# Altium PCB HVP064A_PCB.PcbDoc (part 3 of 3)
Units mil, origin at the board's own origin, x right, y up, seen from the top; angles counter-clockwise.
Board outline 5750 x 4500 mil, 2 copper layers (Top Layer, Bottom Layer), stack 62 mil thick; 174 components, 71 nets, 376 pads, 361 vias.
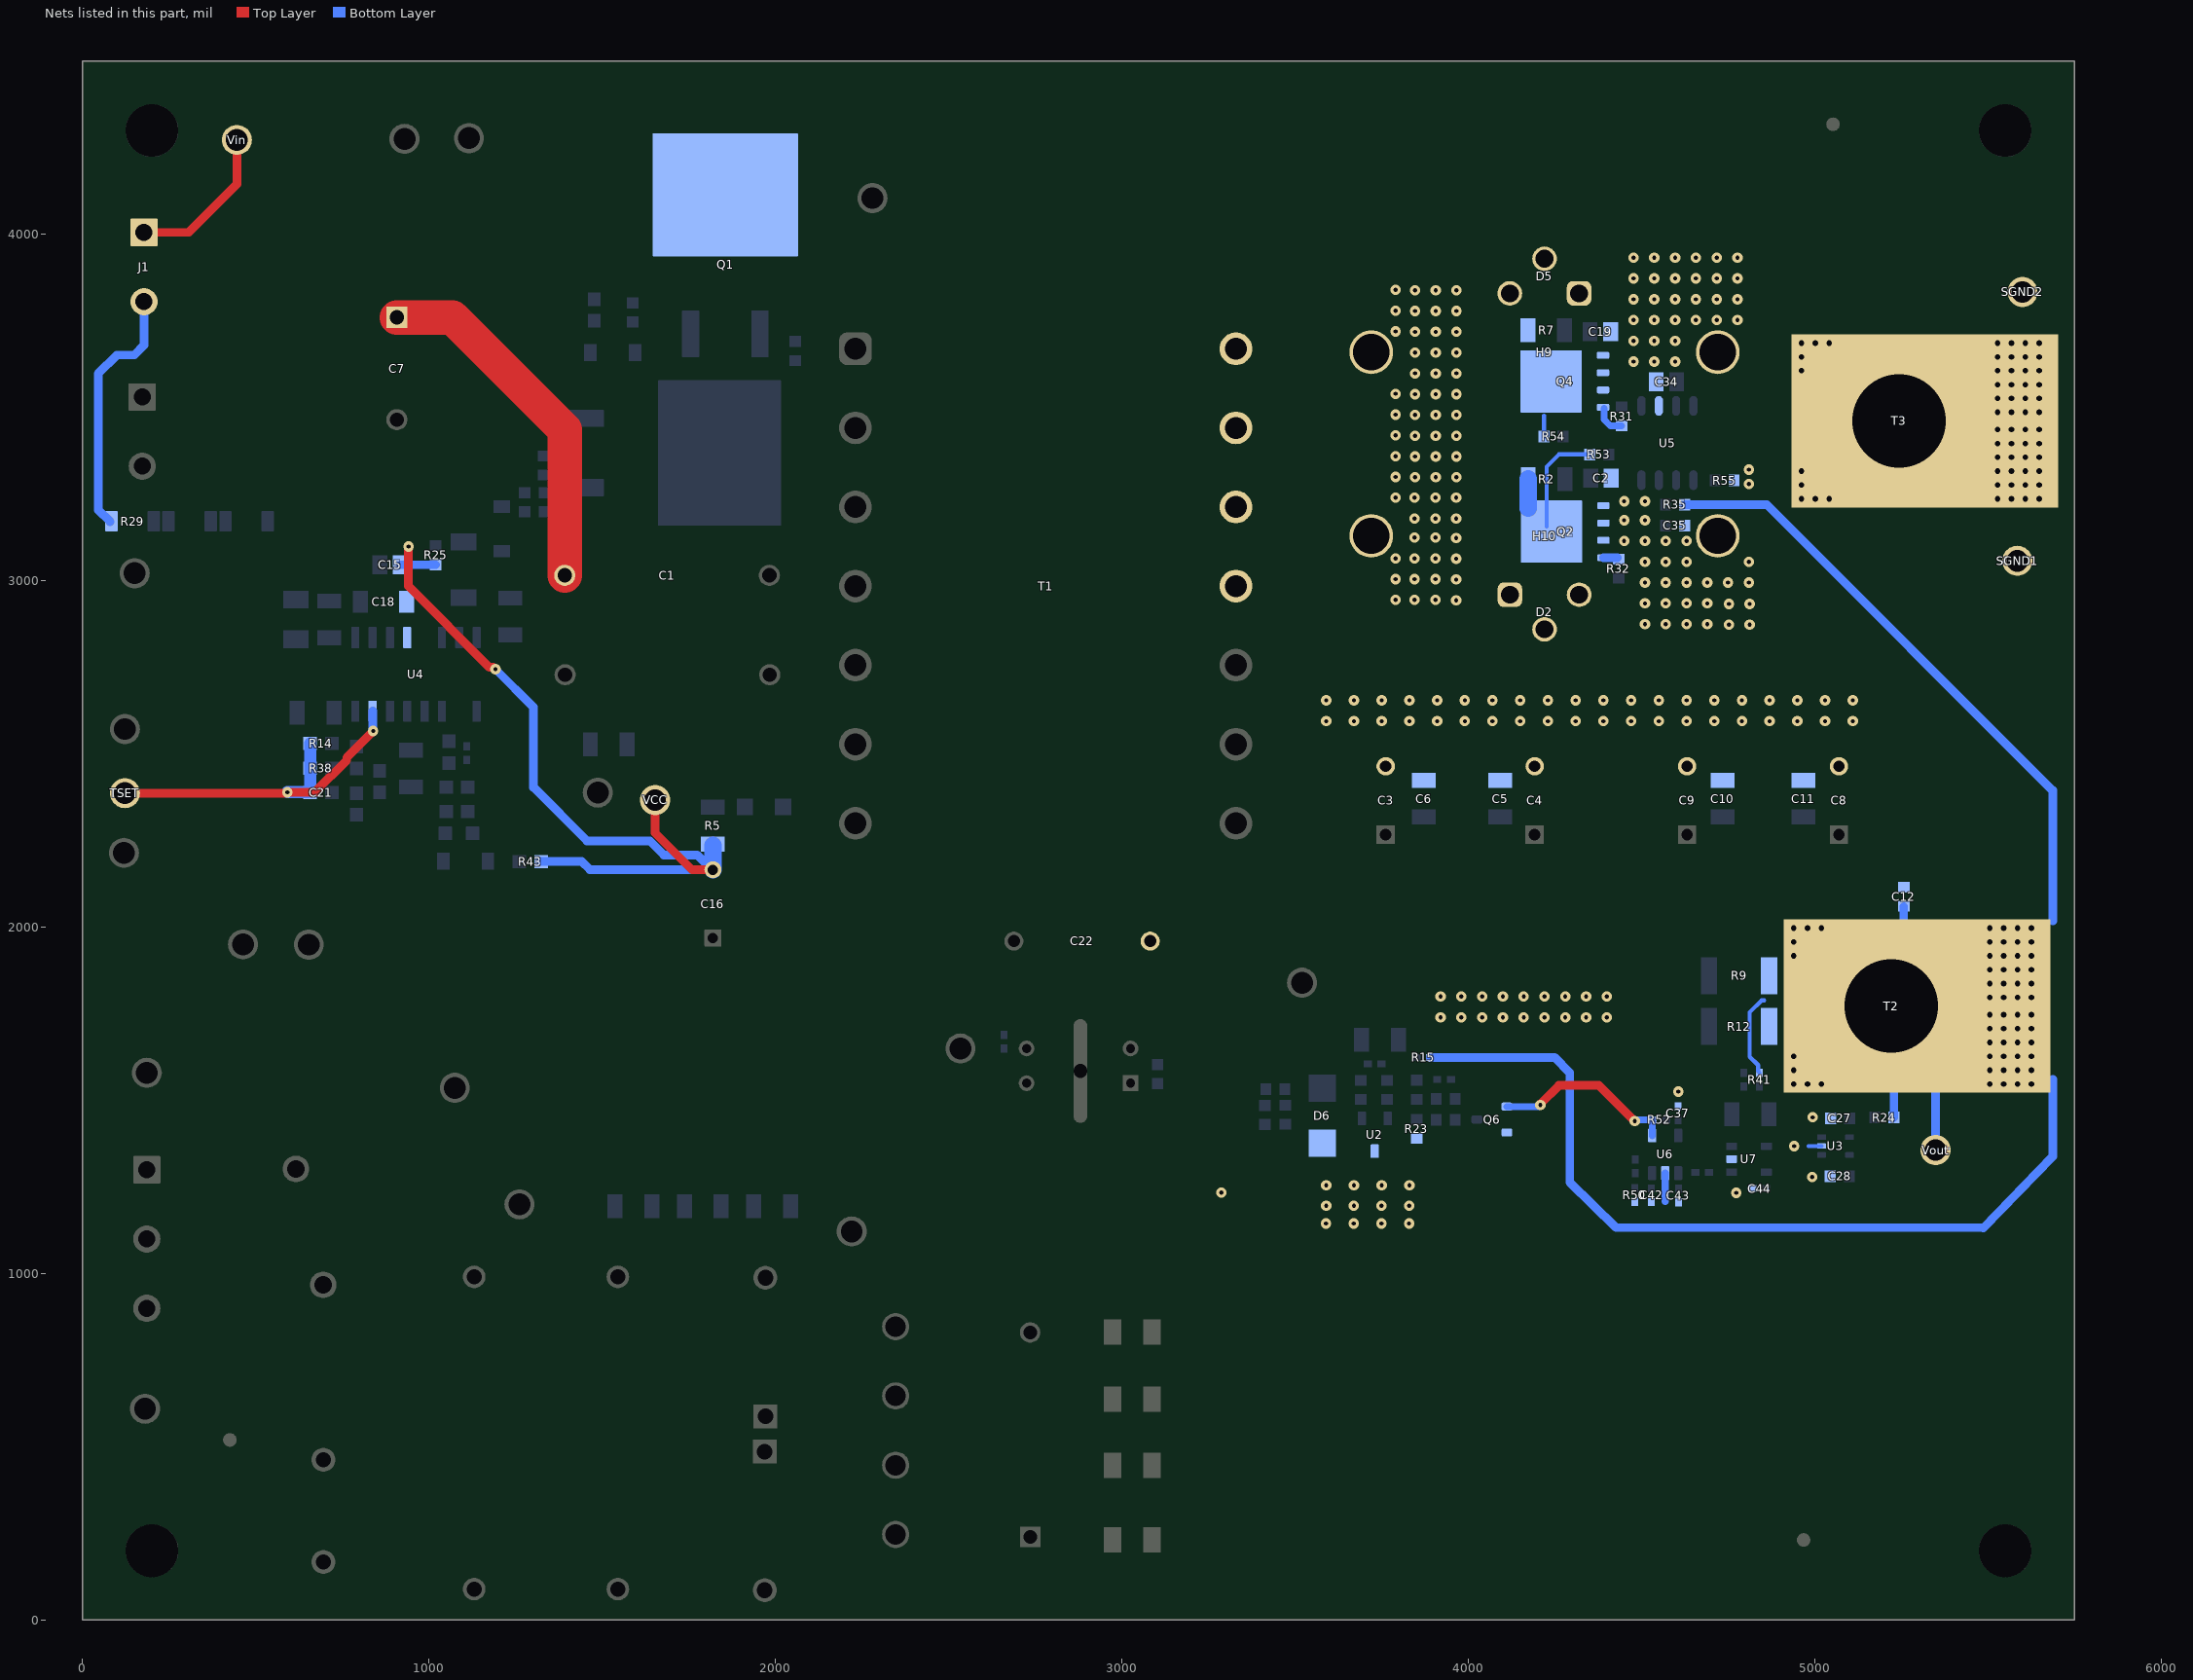
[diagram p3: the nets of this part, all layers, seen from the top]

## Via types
v1: diameter 30, hole 12, Top Layer to Bottom Layer, 243 vias
v2: diameter 32, hole 16, Top Layer to Bottom Layer, 116 vias
v3: diameter 34, hole 16, Top Layer to Bottom Layer, 2 vias

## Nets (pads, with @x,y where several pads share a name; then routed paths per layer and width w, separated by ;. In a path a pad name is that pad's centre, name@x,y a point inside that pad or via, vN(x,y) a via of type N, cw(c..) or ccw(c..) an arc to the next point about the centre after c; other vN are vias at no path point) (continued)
SGND: C2.2 C3.2 C4.2 C5.1 C6.1 C8.2 C9.2 C10.2 C11.2 C12.2 C19.2 C22.1 C27.2 C28.2 C34.2 C35.2 C37.2 C42.1 C43.2 C44.2 D2.1 D2.3 D5.1 D5.3 D6.2 H9.1 H9.2 H10.1 H10.2 Q2.1 Q2.2 Q2.3 Q4.1 Q4.2 Q4.3 Q6.2 R23.1 R50.1 R55.2 SGND1.1 SGND2.1 T3.1 U2.3 U3.2 U5.2 U6.2 U7.2 | length 119.5
  Bottom Layer w12: 4982.39,1368.33 U3.2@5020.03,1368.33
  Bottom Layer w20: 4568.39,1208.33 U6.2@4568.39,1290.2
  other v1: 3589,1145 3669,1145 3749,1145 3829,1145 3589.63,1195.83 3669.63,1195.83 3749.63,1195.83 3829.63,1195.83 4773.39,1233.33 3287,1234 3590,1255 3670,1255 3750,1255 3830,1255 4992.39,1279.33 4940.39,1368.33 4994.39,1451.33 4606.39,1525.33 3920,1740 3980,1740 4040,1740 4100,1740 4160,1740 4220,1740 4280,1740 4340,1740 4400,1740 3920,1800 3980,1800 4040,1800 4100,1800 4160,1800 4220,1800 4280,1800 4340,1800 4400,1800 3590,2595 3670,2595 3750,2595 3830,2595 3910,2595 3990,2595 4070,2595 4150,2595 4230,2595 4310,2595 4390,2595 4470,2595 4550,2595 4630,2595 4710,2595 4790,2595 4870,2595 4950,2595 5030,2595 5110,2595 3590,2655 3670,2655 3750,2655 3830,2655 3910,2655 3990,2655 4070,2655 4150,2655 4230,2655 4310,2655 4390,2655 4470,2655 4550,2655 4630,2655 4710,2655 4790,2655 4870,2655 4950,2655 5030,2655 5110,2655 4752.42,2873.37 4812.42,2873.37 4510,2875 4570,2875 4630,2875 4690,2875 4752.42,2933.37 4812.42,2933.37 4510,2935 4570,2935 4630,2935 4690,2935 3965,2943.83 3790,2945 3845,2945 3905,2945 4510,2995 4570,2995 4630,2995 4690,2995 4750,2995 4810,2995 3965,3003.83 3790,3005 3845,3005 3905,3005 4510,3055 4570,3055 4630,3055 4810,3055 3965,3063.83 3790,3065 3845,3065 3905,3065 4450,3115 4510,3115 4570,3115 4630,3115 3965,3123.83 3845,3125 3905,3125 4450,3175 4510,3175 3845,3180 3905,3180 3965,3180 4450,3230 4510,3230 3790,3240 3845,3240 3905,3240 3965,3240 4810,3280 3846,3299 3906,3299 3966,3299 3790,3300 4810,3320.89 3846,3359 3906,3359 3966,3359 3790,3360 3846,3419 3906,3419 3966,3419 3790,3420 3846,3479 3906,3479 3966,3479 3790,3480 3846,3539 3906,3539 3966,3539 3790,3540 3846,3599 3906,3599 3966,3599 4477,3633 4537,3633 4597,3633 3846,3659 3906,3659 3966,3659 4477,3693 4537,3693 4597,3693 3846,3719 3906,3719 3966,3719 3790,3720 4477,3753 4537,3753 4597,3753 4657,3753 4717,3753 4777,3753 3846,3779 3906,3779 3966,3779 3790,3780 4477,3813 4537,3813 4597,3813 4657,3813 4717,3813 4777,3813 3846,3839 3906,3839 3966,3839 3790,3840 4477,3873 4537,3873 4597,3873 4657,3873 4717,3873 4777,3873 4477,3933 4537,3933 4597,3933 4657,3933 4717,3933 4777,3933
  other v2: 4961.9,3236.62 5001.9,3236.62 5041.9,3236.62 5528.16,3236.62 5568.16,3236.62 5608.16,3236.62 5648.16,3236.62 4961.9,3276.62 5528.16,3276.62 5568.16,3276.62 5608.16,3276.62 5648.16,3276.62 4961.9,3316.62 5528.16,3316.62 5568.16,3316.62 5608.16,3316.62 5648.16,3316.62 5528.16,3356.62 5568.16,3356.62 5608.16,3356.62 5648.16,3356.62 5528.16,3396.62 5568.16,3396.62 5608.16,3396.62 5648.16,3396.62 5528.16,3436.62 5568.16,3436.62 5608.16,3436.62 5648.16,3436.62 5528.16,3486.62 5568.16,3486.62 5608.16,3486.62 5648.16,3486.62 5528.16,3526.62 5568.16,3526.62 5608.16,3526.62 5648.16,3526.62 5528.16,3566.62 5568.16,3566.62 5608.16,3566.62 5648.16,3566.62 4961.9,3606.62 5528.16,3606.62 5568.16,3606.62 5608.16,3606.62 5648.16,3606.62 4961.9,3646.62 5528.16,3646.62 5568.16,3646.62 5608.16,3646.62 5648.16,3646.62 4961.9,3686.62 5001.9,3686.62 5041.9,3686.62 5528.16,3686.62 5568.16,3686.62 5608.16,3686.62 5648.16,3686.62
Standby_Secondary: Q6.1 R52.1 U6.4 | length 533.5
  Top Layer w25: v1@4205.23,1486.77 v1(4208,1486.77) 4208,1489.54 4261.96,1543.5 4377.09,1543.5 v1(4480.39,1440.2)
  Bottom Layer w20: Q6.1@4111.31,1482.4 4203.63,1482.4 v1(4208,1486.77) ; v1@4485.89,1444.33 R52.1@4531.7,1444.33 4531.7,1399.18 U6.4@4530.99,1398.46
TSET/PFC_OFF: C21.1 R14.1 R38.2 TSET.1 U4.7 | length 1051.1
  Top Layer w25: TSET.1@121.87,2387.26 587.14,2387.26 589.65,2389.77 v1(591,2389.77) 669.76,2389.77 762.2,2482.21 762.2,2489.95 v1(838.64,2566.39)
  Bottom Layer w25: U4.7@837,2623.7 837.69,2623.01 837.69,2567.34 v1(838.64,2566.39)
  Bottom Layer w35: v1(591,2389.77) C21.1@650.03,2389.77 ; C21.1@656.67,2391.87 R38.2@656.67,2459.16 R14.1@656.67,2530.47
VCC: C15.1 C16.2 C18.1 R5.1 R25.1 R43.2 U4.12 VCC.1 | length 2450.1
  Top Layer w25: v1(940.45,3099) 940.45,2984.58 1174.46,2750.58 1184.63,2750.58 1190.13,2745.08 v1(1191.48,2745.08) ; VCC.1@1652.45,2367.2 1652.45,2272.19 1758.5,2166.14 C16.2@1819.55,2166.14
  Bottom Layer w25: C15.1@916.4,3046.51 938.05,3046.51 938.17,3046.39 R25.1@1019.15,3046.39 ; v1(1191.48,2745.08) 1301.31,2635.25 1301.31,2403.97 1456.22,2249.06 1637.14,2249.06 1677.73,2208.48 1774.07,2208.48 C16.2@1816.41,2166.14 ; R43.2@1323.26,2189.8 1441.02,2189.8 1464.68,2166.14 C16.2@1816.41,2166.14 ; C16.2@1819.55,2166.14 C16.2@1816.41,2166.14
  Bottom Layer w50: R5.1@1819.55,2236.41 C16.2@1819.55,2166.14
VD1: D5.2 Q4.5 Q4.6 Q4.7 Q4.8 Q4.9@4239.43,3576 R7.2 R54.2 T1.13 T1.14 | length 60.1
  Bottom Layer w12: R54.2@4218.44,3417 4218.44,3477.13
VD2: D2.2 Q2.5 Q2.6 Q2.7 Q2.8 Q2.9@4240.43,3142 R2.2 R53.1 T1.11 T1.12 | length 396.6
  Bottom Layer w12: Q2.9@4226,3156.43 4226,3329.41 4261.59,3365 R53.1@4350.44,3365
  Bottom Layer w50: Q2.8@4172.85,3209.58 R2.2@4172.85,3294
VG1: Q4.4 R31.1 | length 90.7
  Bottom Layer w20: Q4.4@4392.04,3498 4392.04,3465.96 4410.56,3447.44 R31.1@4443,3447.44
VG2: Q2.4 R32.2 | length 39.5
  Bottom Layer w25: Q2.4@4390.04,3067 R32.2@4429.56,3067
VIN: C1.1 C7.1 J1.1 J1.2 Q1.4 R29.2 Vin.1 | length 2226
  Top Layer w25: J1.1@177,4006 306,4006 445,4145 Vin.1@445,4273
  Top Layer w100: C7.1@907,3760.64 1067.36,3760.64 1391.72,3436.28 C1.1@1391.72,3016
  Bottom Layer w25: R29.2@79,3171 45,3205 45,3598 99,3652 149,3652 177,3680 J1.2@177,3806
Vout: C12.1 R9.2 R12.2 R15.2 R24.1 R35.2 R41.2 T2.1 Vout.1 | length 5062.7
  Bottom Layer w12: R41.2@4840.39,1580.01 4836.55,1583.86 4836.55,1602.08 4812.42,1626.21 4812.42,1754.36 4846.84,1788.78 4854.19,1788.78
  Bottom Layer w25: R15.2@3889.69,1624 4249,1624 4293,1580 4293,1264 4427,1133 5487,1132 5687.16,1338.09 5687.16,1561.01 ; R35.2@4624.56,3220 4862,3220 5687.21,2394.79 5687.21,2018.19 ; R24.1@5228.77,1451.03 T2.1@5228.77,1527.71 ; T2.1@5257,1933 C12.1@5257,2059.95 ; T2.1@5297.39,1555.33 T2.1@5297.39,1612.33 ; T2.1@5348.39,1640.83 Vout.1@5348.99,1356.9
  other v2: 4939.47,1547.33 4979.47,1547.33 5019.47,1547.33 5505.73,1547.33 5545.73,1547.33 5585.73,1547.33 5625.73,1547.33 4939.47,1587.33 5505.73,1587.33 5545.73,1587.33 5585.73,1587.33 5625.73,1587.33 4939.47,1627.33 5505.73,1627.33 5545.73,1627.33 5585.73,1627.33 5625.73,1627.33 5505.73,1667.33 5545.73,1667.33 5585.73,1667.33 5625.73,1667.33 5505.73,1707.33 5545.73,1707.33 5585.73,1707.33 5625.73,1707.33 5505.73,1747.33 5545.73,1747.33 5585.73,1747.33 5625.73,1747.33 5505.73,1797.33 5545.73,1797.33 5585.73,1797.33 5625.73,1797.33 5505.73,1837.33 5545.73,1837.33 5585.73,1837.33 5625.73,1837.33 5505.73,1877.33 5545.73,1877.33 5585.73,1877.33 5625.73,1877.33 4939.47,1917.33 5505.73,1917.33 5545.73,1917.33 5585.73,1917.33 5625.73,1917.33 4939.47,1957.33 5505.73,1957.33 5545.73,1957.33 5585.73,1957.33 5625.73,1957.33 4939.47,1997.33 4979.47,1997.33 5019.47,1997.33 5505.73,1997.33 5545.73,1997.33 5585.73,1997.33 5625.73,1997.33
pads on no net: FID1.1 FID2.1 FID3.1 H1.0 H1.MH H2.0 H2.MH H3.0 H3.MH H4.0 H4.MH H5.0 H6.0 H7.0 H8.0 Q2.9@4224.88,3084.91 Q2.9@4224.88,3142 Q2.9@4224.88,3199.09 Q2.9@4258.35,3142 Q2.9@4294.96,3084.91 Q2.9@4294.96,3142 Q2.9@4294.96,3199.09 Q4.9@4223.88,3518.91 Q4.9@4223.88,3576 Q4.9@4223.88,3633.09 Q4.9@4257.35,3576 Q4.9@4293.96,3518.91 Q4.9@4293.96,3576 Q4.9@4293.96,3633.09 T1.1 T1.3 T1.5 U3.1 U3.3
copper on no net: | length 0.3
  Top Layer w6: 5963,3106 5963,3106.34

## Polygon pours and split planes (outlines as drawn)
PGND on Top Layer "TOP_LAYER_PGND_P083" (solid, remove dead copper, pour order 83): 1138.42,2497.49 1140.5,2495.42 1140.5,1924 1236.78,1924 1236.78,2236.74 1236.78,2497.49
SGND on Top Layer "TOP_LAYER_SGND_P078" (solid, remove dead copper, pour order 78): 4465.26,3770 4464,3768.74 4464,3613 4672.91,3613 4691,3631.09 4691,3774
PGND on Top Layer "TOP_LAYER_PGND_P070" (solid, remove dead copper, pour order 70): 2445.82,1409 2705,1409 2705,1864 2543,1864 2447,1768
NetC1_2 on Top Layer "TOP_LAYER_NETC1_2_P046" (solid, remove dead copper, pour order 46): 1910,3086 1910,2748 1910,2683 2039,2683 2204,2907 2255,2907 2314,2966 2314,3011 2239,3086
SGND on Top Layer "TOP_LAYER_SGND_P074" (solid, remove dead copper, pour order 74): 3062.85,4445 4165,4445 4165,3770 4005,3610 4005,3040 4671.4,3040 4671.4,4445 5699,4445 5699,1106 3057.25,1106
SGND on Top Layer "TOP_LAYER_SGND_P076" (solid, remove dead copper, pour order 76): 4133.51,4445 4689,4445 4689,3770 4140,3770
SGND on Top Layer "TOP_LAYER_SGND_P080" (solid, remove dead copper, pour order 80): 4430,3246 4431,3245 4687,3245 4687,3034 4475,3034 4475,3054.34 4429.56,3099.78
BLK on Bottom Layer "BOTTOM_LAYER_BLK_P084" (solid, remove dead copper, pour order 84): 1025.19,2652.2 1025.19,2595.2 1037.53,2582.86 1037.53,2524.8 1048.84,2513.49 1088.22,2513.49 1090.16,2511.54 1119.69,2511.54 1119.69,2570.89 1096.8,2593.78 1061.81,2593.78 1061.81,2653.62 1025.78,2653.62
PGND on Bottom Layer "BOTTOM_LAYER_PGND_P082" (solid, remove dead copper, pour order 82): 1040.06,2488.85 1040.06,2454.84 1092.32,2454.84 1092.32,2315.45 1106.49,2301.28 1106.49,2254.02 1106.49,2236.74 1131.95,2236.74 1236.78,2236.74 1236.78,2497.49 1040.06,2497.49
PGND on Bottom Layer "BOTTOM_LAYER_PGND_P060" (solid, remove dead copper, pour order 60): 936.45,2410.6 936.45,2424.86 940.21,2428.63 940.54,2428.3 1024.66,2428.3 1024.66,2401.15 1023.24,2399.73 1023.24,2148.24 1238.44,2148.24 1238.44,1822 381.44,1822 211,1992.44 211,2299 766.44,2299 769.58,2302.15 769.58,2345.57 856.13,2345.57 856.51,2345.96 861.48,2345.96 865.1,2349.58 865.08,2349.6 865.08,2410.6
VCC on Bottom Layer "BOTTOM_LAYER_VCC_P081" (solid, remove dead copper, pour order 81): 925.19,2902.11 925.19,2806.03 955.72,2806.03 955.72,2906.52 957.19,2907.99 966.66,2907.99 966.66,3004.67 965.55,3005.78 965.55,3117.26 899.31,3117.26 899.31,3066.28 899.31,2902.11
SGND on Bottom Layer "BOTTOM_LAYER_SGND_P028" (solid, remove dead copper, pour order 28): 3055,4461.91 3055,1285 3238,1102 5705,1102 5705,4459.79
IN+ on Bottom Layer "BOTTOM_LAYER_IN+_P008" (solid, remove dead copper, pour order 8): 4790.7,2042.33 4793.77,2045.39 5105,2045.39 5105,2310 5051,2364 3671,2364 3402,2800 3236,2800 3236,2220 3429.07,2042.33 4400,2042.33 4400,1903.97 4666.19,1637.78 4741.4,1637.78 4741.4,2029.33 4754.39,2042.33
PGND on Bottom Layer "BOTTOM_LAYER_PGND_P066" (solid, remove dead copper, pour order 66): 1862.68,2069.68 2123,2330 2123,2354 2452,2354 2710,2096 2710,1594 1387,1594 1037,1944 1037,2069.68
VD2 on Bottom Layer "BOTTOM_LAYER_VD2_P010" (solid, remove dead copper, pour order 10): 3238,3278 3238,2962 3504,2696 4180,2696 4268,2784 4268,3006 4307,3045 4332,3045 4332,3235 4333,3236 4140,3236 4140,3044.98 4172,3012.98 4172,2880 3600,2880 3455,3025 3455,3278
VD1 on Bottom Layer "BOTTOM_LAYER_VD1_P012" (solid, remove dead copper, pour order 12): 3231,3363 3231,3839 3475,4083 4135,4083 4267,3951 4266,3950 4266,3772 4279,3759 4348,3759 4348,3456 4149,3456 4149,3906 4140,3915 4138,3913 3663,3913 3454,3704 3454,3363
VIN on Bottom Layer "BOTTOM_LAYER_VIN_P040" (solid, remove dead copper, pour order 40): 15,4121 1096,4121 1295,4320 2079,4320 2079,3929 2064,3914 1474,3914 1264.62,3704.62 19.52,3704.62
HS on Bottom Layer "BOTTOM_LAYER_HS_P042" (solid, remove dead copper, pour order 42): 1654,3153 2039,3153 2290,3404 2290,3465 2115,3593 1875,3593 1808,3660 1810,3662 1810,3791 1702,3791 1701,3792 1696,3787 1696,3622 1655,3581
PGND on Bottom Layer "BOTTOM_LAYER_PGND_P044" (solid, remove dead copper, pour order 44): 96,3581 1536,3581 1536,3419.83 1501.17,3385 997,3385 894,3282 96,3282
no net on Bottom Layer "BOTTOM_LAYER_NONET_P054" (solid, remove dead copper, pour order 54): 694,2802 803,2802 803,2957 694,2957
NetLG_1 on Bottom Layer "BOTTOM_LAYER_NETLG_1_P056" (solid, remove dead copper, pour order 56): 1255,3287.24 1291.76,3324 1363,3324 1389,3298 1512,3298 1512,3237 1365.5,3237 1255,3237
PGND on Bottom Layer "BOTTOM_LAYER_PGND_P058" (solid, remove dead copper, pour order 58): 868.61,3071 868.61,2581.61 758,2471 758,2141 211,2141 211,2894 388,3071

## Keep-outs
Keep-Out Layer:
  text ".Layer_Name" at 577,-858.49 h60

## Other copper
Top Layer:
  text ".Layer_Name" at 577,-858.49 h60
Bottom Layer:
  region net Vout: 4842.9,1626.51 4877.65,1591.76 4877.65,1554.57 4909.89,1522.33 5700.59,1522.33 5700.59,2025 4842.9,2025
  text ".Layer_Name" at 577,-858.49 h60

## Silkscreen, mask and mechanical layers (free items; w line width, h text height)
Top Overlay:
  text "'.PRJ_Number'.PCB_Rev" at 3066,4353 h108.27
  text "UCC25660EVM-064" at 3714,4350 h108.27
  text "+" at 402,3812 h150
  text "-" at 400,3463 h150
  text "12Vdc 15A max" at 4189.99,1605.68 h100
  text "N" at 401,1273 h100
  text "E" at 401,1100 h100
  text "L" at 401,897 h100
  text ".Layer_Name" at 577,-858.49 h60
Bottom Overlay:
  text "+" at 281,3893 h150
  text "Vin: 365Vdc to 410Vdc" at 980,3646 h100
  text "-" at 292,3423 h150
  text "N" at 399.09,1275 h100
  text "265Vrms Max" at 993,1078 h100
  text "E" at 399.09,1075 h100
  text "L" at 400,895 h100
  text ".Layer_Name" at 577,-858.49 h60
Top Paste:
  text ".Layer_Name" at 577,-858.49 h60
Bottom Paste:
  text ".Layer_Name" at 577,-858.49 h60
Top Solder:
  text ".Layer_Name" at 577,-858.49 h60
  text ".Layer_Name" at 577,-858.49 h60
Bottom Solder:
  text ".Layer_Name" at 577,-858.49 h60
Drill Guide:
  text ".Layer_Name" at 577,-858.49 h60
M1 Board Outline:
  the board outline again, w10
  text ".Layer_Name" at 577,-858.49 h60
M2 Board Dimensions:
  rectangle: 125,-400 500,-275
  rectangle: 0,-275 125,-150
  lines w7: 0,-275 1000,-275 ; 125,-400 125,-150 ; 250,-400 250,-150 ; 500,-400 500,-150 ; 750,-400 750,-150 ; 0,-400 0,-150 1000,-150 1000,-400 0,-400
  text ".Layer_Name" at 577,-858.49 h60
M3 3D STEP Top:
  text ".Layer_Name" at 577,-858.49 h60
M4 3D STEP Bottom:
  text ".Layer_Name" at 577,-858.49 h60
M5 Assembly Top:
  lines w10: -292,-930.17 6308,-930.17 ; -292,-726.83 6310,-726.83 ; -292,-523.5 -292,-1133.5 3713,-1133.5 6310,-1133.5 6310,-523.5 -291.5,-523.5 -291.5,-1133.5 1284,-1133.5 ; 2173,-1133.5 2173,-523.5 ; 3440,-726.83 3440,-523.5 ; 4280,-726.83 4280,-523.5 ; 4902,-1140 4902,-937.17
  text "COMPONENTS MARKED 'DNP' SHOULD NOT BE POPULATED." at 1153.5,-318.5 h60
  text "ASSEMBLY VARIANT:" at 1153,-434 h60
  text ".VariantName" at 2189,-434 h60
  text "PCB VIEWED FROM TOP SIDE" at -228.5,-655.67 h60
  text "BOARD #:" at 2248,-655.67 h60
  text ".PRJ_Number" at 2793.5,-655.67 h60
  text "REV:" at 3638,-655.67 h60
  text ".PCB_Rev" at 3929.5,-655.67 h60
  text "SVN REV:" at 4476,-655.67 h60
  text ".VersionControl_RevNumber" at 4982,-655.67 h60
  text "TID #:" at 2248,-859 h60
  text ".TID" at 2793.5,-859 h60
  text "PLOT NAME =" at -228.5,-1064.34 h60
  text ".plot_File_Name" at 577,-1064.34 h60
  text "GENERATED    :" at 2250,-1064.34 h60
  text ".Print_Date" at 3119.5,-1064.34 h60
  text ".Print_Time" at 3848.5,-1064.34 h60
  text "TEXAS INSTRUMENTS" at 5113,-1064.34 h60
M6 Assembly Bottom:
  lines w10: -292.5,-727.33 6309.5,-727.33 ; -290.5,-930.67 6309.5,-930.67 ; 1115.5,-1140.5 1115.5,-937.67 ; 1737.5,-727.33 1737.5,-524 ; 2577.5,-727.33 2577.5,-524 ; 3844.5,-1134 3844.5,-524 ; 4733.5,-1134 6309,-1134 6309,-524 -292.5,-524 -292.5,-1134 2304.5,-1134 6309.5,-1134 6309.5,-524
  text "COMPONENTS MARKED 'DNP' SHOULD NOT BE POPULATED." at 6102,-318 h60
  text ".VariantName" at 5058,-434 h60
  text "ASSEMBLY VARIANT:" at 6097,-434 h60
  text ".VersionControl_RevNumber" at 1035.5,-656.17 h60
  text "SVN REV:" at 1541.5,-656.17 h60
  text ".PCB_Rev" at 2088,-656.17 h60
  text "REV:" at 2379.5,-656.17 h60
  text ".PRJ_Number" at 3224,-656.17 h60
  text "BOARD #:" at 3769.5,-656.17 h60
  text "PCB VIEWED FROM BOTTOM SIDE" at 6246,-656.17 h60
  text ".TID" at 3224,-859.5 h60
  text "TID #:" at 3769.5,-859.5 h60
  text "TEXAS INSTRUMENTS" at 904.5,-1064.84 h60
  text ".Print_Time" at 2169,-1064.84 h60
  text ".Print_Date" at 2898,-1064.84 h60
  text "GENERATED    :" at 3767.5,-1064.84 h60
  text ".plot_File_Name" at 5440.5,-1064.84 h60
  text "PLOT NAME =" at 6246,-1064.84 h60
M9 Title Sheet:
  drawing of 57 lines, arcs and shapes, not listed
  text "1" at 739.84,8036.5 h70
  text "2" at 3235.5,8036.5 h70
  text "3" at 5724.84,8036.5 h70
  text "4" at 8231.51,8036.5 h70
  text "5" at 10730.5,8036.5 h70
  text "6" at 13235.5,8036.5 h70
  text "A" at -416.5,6893.5 h70
  text "A" at 14383.5,6893.5 h70
  text "B" at -416.5,4513.5 h70
  text "B" at 14383.5,4513.5 h70
  text "C" at -416.5,2138.5 h70
  text "C" at 14383.5,2138.5 h70
  text "PROJECT TITLE:" at 11343.5,277.5 h45
  text ".PRJ_Title" at 11393.5,144.17 h70
  text "DESIGNED FOR:" at 11343.5,-23.5 h45
  text ".PRJ_Customer" at 11393.5,-163.5 h70
  text "D" at -416.5,-231.5 h70
  text "D" at 14383.5,-231.5 h70
  text "FILE NAME:" at 11343.5,-323.5 h45
  text ".PCB_File_Name_No_Path" at 11393.5,-443.5 h70
  text "Texas Instruments (TI) and/or its licensors do not warrant the accuracy or completeness of this specification" at 6374,-605.34 h45
  text "ENGINEER:" at 11343.5,-613.5 h45
  text "LAYOUT BY:" at 12848.5,-613.5 h45
  text "or any information contained therein. TI and/or its licensors do not warrant that this design will meet" at 6329.01,-718 h45
  text ".PRJ_Engineer" at 11393.5,-768.49 h70
  text ".PCB_Layout" at 12899,-768.49 h70
  text "the specifications, will be suitable for your application or fit for any particular purpose, or will operate in" at 6329.01,-830.67 h45
  text ".Layer_Name" at 577,-858.49 h60
  text "ALTIUM DESIGNER VERSION:" at 12848.5,-923.5 h45
  text "an implementation. TI and/or its licensors do not warrant that the design is production worthy. You should" at 6329.01,-943.33 h45
  text "completely validate and test your design implementation to confirm the system functionality for your application." at 6374,-1056 h45
  text ".print_Scale" at 11393.5,-1056.83 h70
  text ".Application_BuildNumber" at 12899,-1056.83 h70
  text "1" at 739.84,-1263.5 h70
  text "2" at 3235.5,-1263.5 h70
  text "3" at 5724.84,-1263.5 h70
  text "4" at 8231.51,-1263.5 h70
  text "5" at 10730.5,-1263.5 h70
  text "6" at 13235.5,-1263.5 h70
M10 Fab Notes:
  drawing of 189 lines, arcs and shapes, not listed
  text "DESIGN INFORMATION" at 12382.02,6356.17 h60
  text "MIN. TRACK WIDTH:" at 11737.46,6224.05 h60
  text "8" at 12833.7,6224.05 h60
  text "MIL" at 12988.46,6224.05 h60
  text "MIN. CLEARANCE:" at 11737.46,6099.92 h60
  text "0.2" at 12773.7,6099.93 h60
  text "mm" at 12988.46,6099.92 h60
  text "MIN. VIA PAD SIZE:" at 11737.46,5975.8 h60
  text "24" at 12803.71,5975.8 h60
  text "MIL" at 12988.46,5975.8 h60
  text "0.05mm (2MIL)" at 12432.46,5845.9 h60
  text "MINIMUM ANNULAR RING" at 11408.23,5837.67 h60
  text "EXTERNAL" at 13140.46,5837.67 h60
  text "PER" at 11608.23,5727.55 h60
  text "IPC-D-275 CLASS 2 LEVEL C" at 11828.23,5727.54 h60
  text "MIL, HOLES" at 13316.46,5627.07 h60
  text "+/-" at 12924,5618.48 h60
  text "+/-" at 13778,5618.48 h60
  text "REGISTRATION TOLERANCES:" at 11408.23,5617.42 h60
  text "METAL" at 12608,5617.42 h60
  text "5" at 13184.2,5617.42 h60
  text "3" at 14017.2,5617.42 h60
  text "MIL" at 14133.46,5617.42 h60
  text "HOLE SIZE TOLERANCE (UNLESS OTHERWISE SPECIFIED):" at 11408.23,5519.1 h60
  text "+/-" at 13778,5516.23 h60
  text "3" at 14017.2,5515.17 h60
  text "MIL" at 14133.46,5515.17 h60
  text "MATERIAL:" at 11333.46,5377.52 h60
  text "FR-4 High Tg" at 12319.9,5249 h60
  text "X" at 12175.46,5241.01 h60
  text "FR-408" at 11754.46,5236.49 h60
  text "OTHER" at 13242.46,5236.49 h60
  text "62 MIL (1.6mm) +/-10%" at 12074.56,5093.46 h60
  text "X" at 11954.46,5091.01 h60
  text "THICKNESS:" at 11408.23,5085.24 h60
  text "OTHER" at 13359.46,5085.24 h60
  text "TOLERANCE:" at 11408.23,4946.92 h60
  text "X" at 12256.46,4946.92 h60
  text "ANSI IPC-6012 TYPE 3 CLASS 2" at 12434.48,4946.92 h60
  text "OTHER +/-" at 12434.46,4802.73 h60
  text "BOW & TWIST:" at 11408.23,4657.54 h60
  text "X" at 12256.46,4657.54 h60
  text "ANSI IPC-6012 TYPE 3 CLASS 2" at 12434.48,4657.54 h60
  text "OTHER +/-" at 12434.46,4510.85 h60
  text "DRILLING:" at 11333.46,4380.23 h60
  text "NC_DRILL FILES" at 13094.46,4275.04 h60
  text "REFERENCE:" at 11408.23,4271.1 h60
  text "X" at 12065.46,4271.01 h60
  text "AS SHOWN" at 12243.46,4271.1 h60
  text "X" at 12966.46,4271.1 h60
  text "OTHER" at 13392.46,4128.85 h60
  text "PTH COPPER THICKNESS:" at 11407.91,4125.32 h60
  text "X" at 12547.14,4125.32 h60
  text "20-30 um" at 12675.14,4125.32 h60
  text "BOARD FINISH:" at 11333.46,3977.73 h60
  text "SILKSCREEN:" at 11488.68,3867.6 h60
  text "X" at 12446.46,3867.6 h60
  text "TOP" at 12563.46,3867.6 h60
  text "X" at 12956.46,3867.6 h60
  text "BOTTOM" at 13074.46,3867.6 h60
  text "SILKSCREEN COLOR:" at 11488.68,3712.41 h60
  text "X" at 12445.46,3712.41 h60
  text "WHITE" at 12563.46,3712.41 h60
  text "OTHER" at 13074.46,3712.41 h60
  text "X" at 12576.46,3568.96 h60
  text "GREEN" at 12694.46,3568.96 h60
  text "OTHER" at 13312.46,3568.96 h60
  text "SOLDER RESIST COLOR:" at 11488.68,3562.1 h60
  text "X" at 12576.46,3414.71 h60
  text "MATTE" at 12694.46,3414.71 h60
  text "SEMI-GLOSS" at 13312,3414.07 h60
  text "IMMERSION GOLD (ENIG)" at 12394.46,3241.94 h60
  text "ENEPIG" at 13732,3234.72 h60
  text "SURFACE FINISH:" at 11333.46,3233.72 h60
  text "X" at 12216.46,3233.72 h60
  text "IMM. TIN/SILVER OR EQUIV" at 11663,3096.4 h60
  text "OTHER" at 13094.46,3092.47 h60
  text "ARRAY/PANEL:" at 11333.46,2937.09 h60
  text "CUT AND TRIM PER M1 BOARD OUTLINE" at 12394.46,2928.87 h60
  text "N.C. ROUTE" at 12394.46,2792.9 h60
  text "X" at 13082.46,2792.9 h60
  text "V. SCORE" at 13260.46,2792.9 h60
  text "CERTIFICATION:" at 11333.46,2663.77 h60
  text "MATERIALS AND WORKMANSHIP FOR ALL PCBS" at 12058.46,2663.77 h60
  text "TO MEET OR EXCEED THE REQUIREMENTS OF:" at 12058.46,2569.71 h60
  text "X" at 11695.97,2441.08 h60
  text "ANSI IPC-A-600F CLASS ->" at 11823.96,2441.08 h60
  text "X" at 13471.97,2441.08 h60
  text "2" at 13581.96,2441.08 h60
  text "1" at 13266.96,2439.58 h60
  text "3" at 13935.96,2439.58 h60
  text "X" at 12507.97,2293.39 h60
  text "RoHS" at 12635.96,2293.39 h60
  text "OTHER" at 13280.36,2293.39 h60
  text "PER ORDER" at 13677.42,2293.39 h60
  text "ALL BOARDS MUST MEET OR EXCEED UL94-V0 REQUIREMENTS." at 11361,2139.57 h60
  text "PCB MUST BEAR THE UL94V-0 UL REGISTERED MATERIAL ID NUMBER" at 11361,2023.5 h60
  text "ADDITIONAL REQUIREMENTS:" at 11333.46,1854.08 h60
  text "MICROSECTION:" at 11408.23,1746.95 h60
  text "YES" at 12313.96,1746.95 h60
  text "REQUIRED" at 13175.46,1602.62 h60
  text "BARE BOARD ELEC. TEST:" at 11408.23,1599.76 h60
  text "NONE" at 12713.96,1599.76 h60
  text "X" at 13057.46,1599.76 h60
  text "PER ORDER" at 13767.46,1599.76 h60
  text "XX MIL VIAS REQUIRE NON-CONDUCTIVE FILL AND PLANARIZE" at 11576.38,1394.82 h59
  text "XX MIL VIAS REQUIRE CONDUCTIVE FILL AND PLANARIZE" at 11584.38,1290.84 h60
  text "OUTER XX MIL TRACES REQUIRE 50 OHM SINGLE-ENDED IMPEDANCE" at 11583.39,1127.46 h58
  text "LAYER 2 & 3 (INNER LAYERS) XX MIL WIDE, XX MIL SPACE / TRACES REQUIRE 100 OHM DIFFERENTIAL IMPEDANCE" at 11575.39,891.74 h60
  text ".Layer_Name" at 577,-858.49 h60
M11 Gerber Information:
  lines w10: -292,-930.17 6308,-930.17 ; -292,-726.83 6310,-726.83 ; -292,-523.5 -292,-1133.5 3713,-1133.5 6310,-1133.5 6310,-523.5 -291.5,-523.5 -291.5,-1133.5 1284,-1133.5 ; 2173,-1133.5 2173,-523.5 ; 3440,-726.83 3440,-523.5 ; 4280,-726.83 4280,-523.5 ; 4902,-1140 4902,-937.17
  text "ALL ARTWORK VIEWED FROM TOP SIDE" at -228.5,-655.67 h60
  text "BOARD #:" at 2248,-655.67 h60
  text ".PRJ_Number" at 2793.5,-655.67 h60
  text "REV:" at 3638,-655.67 h60
  text ".PCB_Rev" at 3929.5,-655.67 h60
  text "SVN REV:" at 4476,-655.67 h60
  text ".VersionControl_RevNumber" at 4982,-655.67 h60
  text "LAYER NAME =" at -228.5,-858.49 h60
  text "TID #:" at 2248,-859 h60
  text ".TID" at 2793.5,-859 h60
  text "PLOT NAME =" at -228.5,-1064.34 h60
  text ".plot_File_Name" at 577,-1064.34 h60
  text "GENERATED    :" at 2250,-1064.34 h60
  text ".Print_Date" at 3119.5,-1064.34 h60
  text ".Print_Time" at 3848.5,-1064.34 h60
  text "TEXAS INSTRUMENTS" at 5113,-1064.34 h60
M12 Stackup:
  drawing of 191 lines, arcs and shapes, not listed
  text "Layer" at 4473.5,6398.5 h60
  text "Name" at 4883.41,6398.5 h60
  text "Material" at 5813.16,6398.5 h60
  text "Thickness" at 6672.92,6398.5 h60
  text "Constant" at 7322.76,6398.5 h60
  text "Board Layer Stack" at 7892.62,6398.5 h60
  text "Top Overlay" at 4883.41,6278.5 h60
  text "Top Solder" at 4883.41,6158.5 h60
  text "Solder Resist" at 5813.16,6158.5 h60
  text "0.40mil" at 6672.92,6158.5 h60
  text "3.5" at 7322.76,6158.5 h60
  text "1" at 4473.5,6038.5 h60
  text "Top Layer" at 4883.41,6038.5 h60
  text "2.80mil" at 6672.92,6038.5 h60
  text "Dielectric1" at 4883.41,5918.5 h60
  text "FR-4 High Tg" at 5813.16,5918.5 h60
  text "56.40mil" at 6672.92,5918.5 h60
  text "4.8" at 7322.76,5918.5 h60
  text "2" at 4473.5,5798.5 h60
  text "Bottom Layer" at 4883.41,5798.5 h60
  text "2.80mil" at 6672.92,5798.5 h60
  text "Bottom Solder" at 4883.41,5678.5 h60
  text "Solder Resist" at 5813.16,5678.5 h60
  text "0.40mil" at 6672.92,5678.5 h60
  text "3.5" at 7322.76,5678.5 h60
  text "Bottom Overlay" at 4883.41,5558.5 h60
  text ".Layer_Name" at 577,-858.49 h60
M13 Component Bodies Top:
  text ".Layer_Name" at 577,-858.49 h60
M14 Component Bodies Bottom:
  text ".Layer_Name" at 577,-858.49 h60
M15 Courtyards Top:
  text ".Layer_Name" at 577,-858.49 h60
M16 Courtyards Bottom:
  text ".Layer_Name" at 577,-858.49 h60
Drill Drawing:
  drawing of 181 lines, arcs and shapes, not listed
  text "Symbol" at 7328.86,3040.45 h72
  text "Count" at 7629.42,3040.45 h72
  text "Hole Size" at 7932.06,3040.45 h72
  text "Plated" at 8524.86,3040.45 h72
  text "Hole Type" at 8784,3040.45 h72
  text "Drill Layer Pair" at 9159.16,3040.45 h72
  text "Hole Tolerance" at 9883.49,3040.45 h72
  text "243" at 7629.42,2916.13 h60
  text "12.00mil (0.305mm)" at 7932.06,2916.13 h60
  text "PTH" at 8524.86,2916.13 h60
  text "Round" at 8784,2916.13 h60
  text "Top Layer - Bottom Layer" at 9159.16,2916.13 h60
  text "118" at 7629.42,2791.81 h60
  text "16.00mil (0.406mm)" at 7932.06,2791.81 h60
  text "PTH" at 8524.86,2791.81 h60
  text "Round" at 8784,2791.81 h60
  text "Top Layer - Bottom Layer" at 9159.16,2791.81 h60
  text "4" at 7629.42,2667.49 h60
  text "25.59mil (0.650mm)" at 7932.06,2667.49 h60
  text "PTH" at 8524.86,2667.49 h60
  text "Round" at 8784,2667.49 h60
  text "Top Layer - Bottom Layer" at 9159.16,2667.49 h60
  text "2" at 7629.42,2543.17 h60
  text "29.53mil (0.750mm)" at 7932.06,2543.17 h60
  text "PTH" at 8524.86,2543.17 h60
  text "Round" at 8784,2543.17 h60
  text "Top Layer - Bottom Layer" at 9159.16,2543.17 h60
  text "8" at 7629.42,2418.85 h60
  text "33.47mil (0.850mm)" at 7932.06,2418.85 h60
  text "PTH" at 8524.86,2418.85 h60
  text "Round" at 8784,2418.85 h60
  text "Top Layer - Bottom Layer" at 9159.16,2418.85 h60
  text "2" at 7629.42,2294.53 h60
  text "35.43mil (0.900mm)" at 7932.06,2294.53 h60
  text "PTH" at 8524.86,2294.53 h60
  text "Round" at 8784,2294.53 h60
  text "Top Layer - Bottom Layer" at 9159.16,2294.53 h60
  text "2" at 7629.42,2170.21 h60
  text "39.37mil (1.000mm)" at 7932.06,2170.21 h60
  text "PTH" at 8524.86,2170.21 h60
  text "Round" at 8784,2170.21 h60
  text "Top Layer - Bottom Layer" at 9159.16,2170.21 h60
  text "1" at 7629.42,2045.89 h60
  text "40.00mil (1.016mm)" at 7932.06,2045.89 h60
  text "NPTH" at 8524.86,2045.89 h60
  text "Slot" at 8784,2045.89 h60
  text "Top Layer - Bottom Layer" at 9159.16,2045.89 h60
  text "6" at 7629.42,1921.57 h60
  text "41.34mil (1.050mm)" at 7932.06,1921.57 h60
  text "PTH" at 8524.86,1921.57 h60
  text "Round" at 8784,1921.57 h60
  text "Top Layer - Bottom Layer" at 9159.16,1921.57 h60
  text "C" at 7303.57,1911.58 h55.25
  text "6" at 7629.42,1797.25 h60
  text "43.31mil (1.100mm)" at 7932.06,1797.25 h60
  text "PTH" at 8524.86,1797.25 h60
  text "Round" at 8784,1797.25 h60
  text "Top Layer - Bottom Layer" at 9159.16,1797.25 h60
  text "4" at 7629.42,1672.93 h60
  text "45.28mil (1.150mm)" at 7932.06,1672.93 h60
  text "PTH" at 8524.86,1672.93 h60
  text "Round" at 8784,1672.93 h60
  text "Top Layer - Bottom Layer" at 9159.16,1672.93 h60
  text "7" at 7629.42,1548.61 h60
  text "49.21mil (1.250mm)" at 7932.06,1548.61 h60
  text "PTH" at 8524.86,1548.61 h60
  text "Round" at 8784,1548.61 h60
  text "Top Layer - Bottom Layer" at 9159.16,1548.61 h60
  text "8" at 7629.42,1424.29 h60
  text "51.18mil (1.300mm)" at 7932.06,1424.29 h60
  text "PTH" at 8524.86,1424.29 h60
  text "Round" at 8784,1424.29 h60
  text "Top Layer - Bottom Layer" at 9159.16,1424.29 h60
  text "E" at 7303.57,1414.3 h55.25
  text "4" at 7629.42,1299.97 h60
  text "59.06mil (1.500mm)" at 7932.06,1299.97 h60
  text "PTH" at 8524.86,1299.97 h60
  text "Round" at 8784,1299.97 h60
  text "Top Layer - Bottom Layer" at 9159.16,1299.97 h60
  text "14" at 7629.42,1175.65 h60
  text "62.99mil (1.600mm)" at 7932.06,1175.65 h60
  text "PTH" at 8524.86,1175.65 h60
  text "Round" at 8784,1175.65 h60
  text "Top Layer - Bottom Layer" at 9159.16,1175.65 h60
  text "+/-1.18mil" at 9883.49,1175.65 h60
  text "A" at 7303.57,1165.66 h55.25
  text "22" at 7629.42,1051.33 h60
  text "63.00mil (1.600mm)" at 7932.06,1051.33 h60
  text "PTH" at 8524.86,1051.33 h60
  text "Round" at 8784,1051.33 h60
  text "Top Layer - Bottom Layer" at 9159.16,1051.33 h60
  text "4" at 7629.42,927.01 h60
  text "105.12mil (2.670mm)" at 7932.06,927.01 h60
  text "PTH" at 8524.86,927.01 h60
  text "Round" at 8784,927.01 h60
  text "Top Layer - Bottom Layer" at 9159.16,927.01 h60
  text "B" at 7303.57,917.02 h55.25
  text "4" at 7629.42,802.69 h60
  text "152.00mil (3.861mm)" at 7932.06,802.69 h60
  text "NPTH" at 8524.86,802.69 h60
  text "Round" at 8784,802.69 h60
  text "Top Layer - Bottom Layer" at 9159.16,802.69 h60
  text "2" at 7629.42,678.37 h60
  text "270.00mil (6.858mm)" at 7932.06,678.37 h60
  text "PTH" at 8524.86,678.37 h60
  text "Round" at 8784,678.37 h60
  text "Top Layer - Bottom Layer" at 9159.16,678.37 h60
  text "D" at 7303.57,668.38 h55.25
  text "461 Total" at 7629.42,554.05 h60
  text "Slot definitions :" at 7328.86,467.03 h60
  text "Routed Path Length" at 7779.57,467.03 h60
  text "= Calculated from tool start centre position to tool end centre position." at 8319.31,467.03 h60
  text "Hole Length" at 7779.57,417.3 h60
  text "= Routed Path Length + Tool Size = Slot length as defined in the PCB layout" at 8119.51,417.3 h60
  text ".Layer_Name" at 577,-858.49 h60
M17 Embedded Cavity:
  text ".Layer_Name" at 577,-858.49 h60
M18 Embedded Assembly:
  text ".Layer_Name" at 577,-858.49 h60
M19 Embedded Keepout:
  text ".Layer_Name" at 577,-858.49 h60

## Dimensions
0,0 to 5750,0 on M2 Board Dimensions
0,0 to 0,4500 on M2 Board Dimensions
0,-400 to 1000,-400 on M2 Board Dimensions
